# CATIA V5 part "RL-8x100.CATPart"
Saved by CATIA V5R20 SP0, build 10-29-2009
Part number: _RL-8x100
Definition: NONE
Nomenclature: _RL-8x100
Source: Unknown
Description: PART-_RL-8x100-DESC
Bounding box of the stored display mesh (mm): x -100 to 9.5, y -4.95 to 4.95, z -4.95 to 4.95
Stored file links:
  C:\Users\Utente\Desktop\IO LAVORO\3D X SITO CF\X SITO\PLASTICA\RL\RL-8x100.CATPart
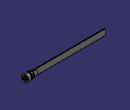
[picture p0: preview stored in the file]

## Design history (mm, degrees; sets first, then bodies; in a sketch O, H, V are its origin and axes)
Body1 "_RL-8x100" (main body)
  Solid1: solid without history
